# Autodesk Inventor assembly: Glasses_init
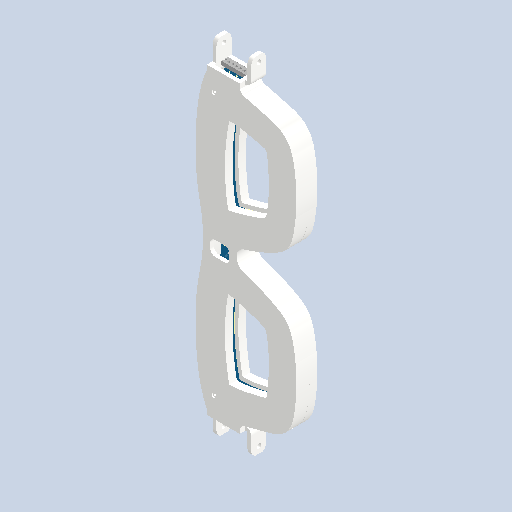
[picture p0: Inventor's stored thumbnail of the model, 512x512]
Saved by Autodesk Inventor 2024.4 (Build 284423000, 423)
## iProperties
Created: 2025-05
Part Number: Glasses_init
Document SubType Name: Assembly
Designer: AdminForWorker
Title: Glasses_init v17
Author: AdminForWorker
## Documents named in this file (3)
- c:\worker\convert-fusion-r02-cosv3\tmp\job-1\2\temp\files\be827049-a7f2-47ea-a815-8d9efd6bfce9\Glasses_init v17.iam
- c:\worker\convert-fusion-r02-cosv3\tmp\job-1\2\temp\files\be827049-a7f2-47ea-a815-8d9efd6bfce9\3D_PCB1-screw_2025-04-08 v1.iam
- c:\worker\convert-fusion-r02-cosv3\tmp\job-1\2\temp\files\be827049-a7f2-47ea-a815-8d9efd6bfce9\Part30.ipt
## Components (2 placed, 2 different names)
1. 3D_PCB1-screw_2025-04-08 v1:1 [sub-assembly]
2. Part30
